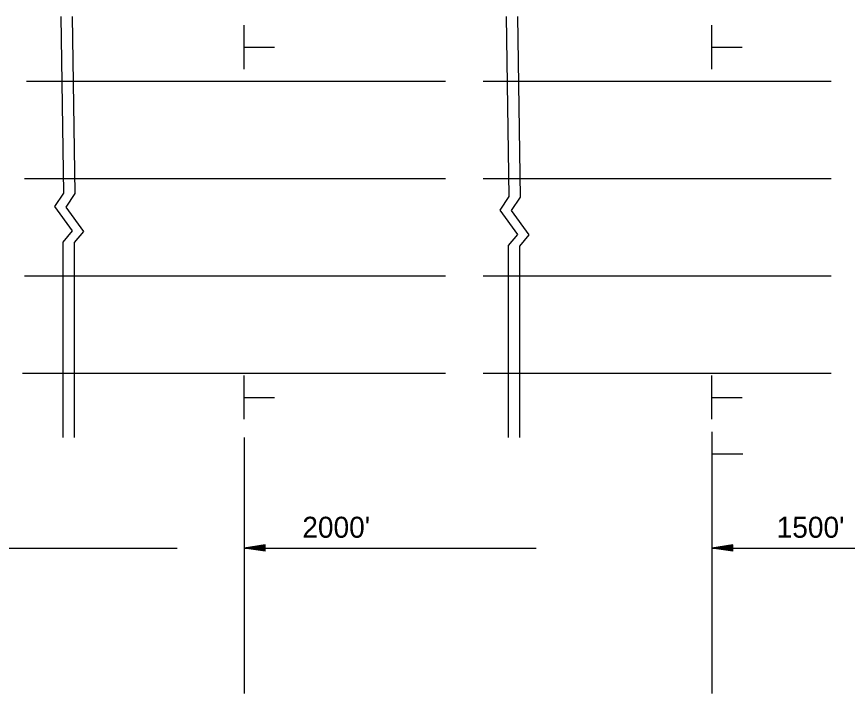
# Model space of a CAD drawing. Extents: x -100 to 745, y -1581 to -107.
# Drawn here: x 269.76 to 295.91, y -765.56 to -744.27 of the extents above; entities that cross this region are included whole.
import ezdxf

# ---------------------------------------------------------------- set-up
doc = ezdxf.new("R2010")
doc.units = 0
doc.layers.add('Default', color=7, linetype='Continuous')

msp = doc.modelspace()

# ---------------------------------------------------------------- linework, layer by layer
at = {"layer": 'Default'}
for p, q in [((276.923, -745.916), (276.923, -744.538)), ((291.636, -745.916), (291.636, -744.538)), ((276.943, -745.231), (277.884, -745.231)), ((291.656, -745.231), (292.597, -745.231)), ((270.07, -746.294), (283.265, -746.294)), ((284.441, -746.294), (295.401, -746.294)), ((270.01, -749.356), (283.265, -749.356)), ((284.441, -749.356), (295.401, -749.356)), ((270.01, -752.419), (283.265, -752.419)), ((284.441, -752.419), (295.401, -752.419)), ((269.95, -755.481), (283.265, -755.481)), ((284.441, -755.481), (295.401, -755.481)), ((276.923, -756.938), (276.923, -755.56)), ((291.636, -756.938), (291.636, -755.56)), ((276.943, -756.252), (277.884, -756.252)), ((291.656, -756.252), (292.597, -756.252)), ((291.651, -758.708), (291.651, -757.33)), ((276.923, -757.508), (276.923, -765.561)), ((291.636, -757.508), (291.636, -765.561)), ((291.672, -758.023), (292.612, -758.023)), ((265.621, -760.99), (274.814, -760.99)), ((277.583, -760.891), (276.923, -760.99)), ((276.923, -760.99), (286.116, -760.99)), ((277.583, -761.089), (276.923, -760.99)), ((277.583, -760.907), (277.033, -760.99)), ((277.583, -761.072), (277.033, -760.99)), ((277.583, -760.924), (277.147, -760.99)), ((277.583, -761.056), (277.147, -760.99)), ((277.583, -760.941), (277.257, -760.99)), ((277.583, -761.039), (277.257, -760.99)), ((277.583, -760.957), (277.369, -760.99)), ((277.583, -761.022), (277.369, -760.99)), ((277.583, -760.974), (277.479, -760.99)), ((277.583, -761.005), (277.479, -760.99)), ((277.583, -761.089), (277.583, -760.891)), ((292.297, -760.891), (291.636, -760.99)), ((291.636, -760.99), (300.829, -760.99)), ((292.297, -761.089), (291.636, -760.99)), ((292.297, -760.907), (291.746, -760.99)), ((292.297, -761.072), (291.746, -760.99)), ((292.297, -760.924), (291.86, -760.99)), ((292.297, -761.056), (291.86, -760.99)), ((292.297, -760.941), (291.97, -760.99)), ((292.297, -761.039), (291.97, -760.99)), ((292.297, -760.957), (292.082, -760.99)), ((292.297, -761.022), (292.082, -760.99)), ((292.297, -760.974), (292.192, -760.99)), ((292.297, -761.005), (292.192, -760.99)), ((292.297, -761.089), (292.297, -760.891))]:
    msp.add_line(p, q, dxfattribs=at)
for points in [[(271.158, -744.267), (271.243, -749.82), (270.957, -750.246), (271.514, -751.008), (271.221, -751.36), (271.22, -757.508)], [(271.51, -744.267), (271.595, -749.835), (271.309, -750.26), (271.866, -751.023), (271.573, -751.375), (271.572, -757.508)], [(285.172, -744.267), (285.258, -749.931), (284.972, -750.357), (285.53, -751.119), (285.236, -751.472), (285.235, -757.508)], [(285.524, -744.267), (285.61, -749.946), (285.324, -750.371), (285.882, -751.134), (285.588, -751.486), (285.587, -757.508)]]:
    msp.add_lwpolyline(points, dxfattribs=at)

# ---------------------------------------------------------------- texts
for s, p in [("2000'", (278.754, -760.664)), ("1500'", (293.681, -760.664))]:
    msp.add_text(s, height=0.6606, dxfattribs=at).set_placement(p)

doc.saveas('drawing.dxf')
